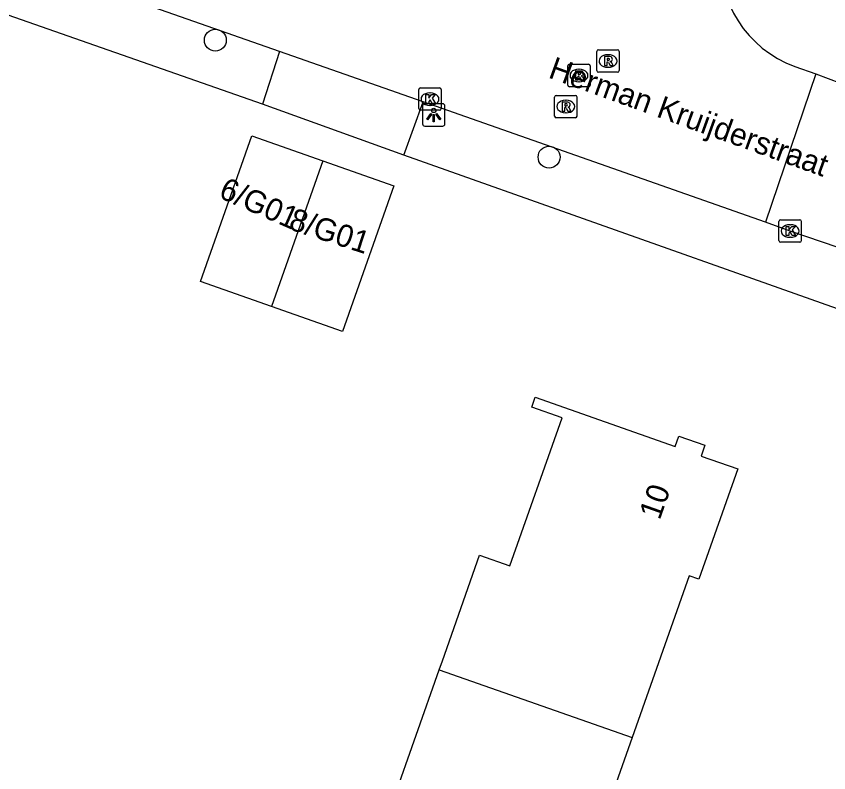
# Model space of a CAD drawing. Extents: x 163268 to 164360, y 381529 to 382285.
# Drawn here: x 163693.84 to 163730.1, y 381686.62 to 381720.39 of the extents above; entities that cross this region are included whole.
import ezdxf

# ---------------------------------------------------------------- set-up
doc = ezdxf.new("R2010")
doc.units = 0
for name, color, linetype in [('IMGEO_Boom', 7, 'Continuous'), ('IMGEO_Kolk', 7, 'Continuous'), ('IMGEO_Lichtpunt', 7, 'Continuous'), ('IMGEO_Openbare_ruimte_label', 7, 'Continuous'), ('IMGEO_Pand', 7, 'Continuous'), ('IMGEO_Pand_nummerreeks', 7, 'Continuous'), ('IMGEO_Rijbaan_lokaal_open', 7, 'Continuous'), ('IMGEO_Rioolput', 7, 'Continuous'), ('IMGEO_Voetpad_open', 7, 'Continuous')]:
    doc.layers.add(name, color=color, linetype=linetype)

msp = doc.modelspace()

# ---------------------------------------------------------------- linework, layer by layer
at = {"layer": 'IMGEO_Boom'}
for centre in [(163702.721, 381719.324), (163717.618, 381714.104)]:
    msp.add_circle(centre, 0.489, dxfattribs=at)
at = {"layer": 'IMGEO_Kolk'}
for p, q in [((163711.802, 381716.267), (163711.802, 381717.119)), ((163711.877, 381717.193), (163712.729, 381717.193)), ((163712.29, 381716.973), (163712.315, 381716.973)), ((163712.803, 381717.119), (163712.803, 381716.267)), ((163712.313, 381716.413), (163712.288, 381716.413)), ((163712.729, 381716.193), (163711.877, 381716.193)), ((163727.876, 381710.379), (163727.876, 381711.231)), ((163727.951, 381711.305), (163728.803, 381711.305)), ((163728.877, 381711.231), (163728.877, 381710.379)), ((163728.364, 381711.085), (163728.389, 381711.085)), ((163728.387, 381710.525), (163728.362, 381710.525)), ((163728.803, 381710.305), (163727.951, 381710.305))]:
    msp.add_line(p, q, dxfattribs=at)
for points in [[(163711.802, 381716.267), (163711.802, 381717.119)], [(163711.877, 381717.193), (163712.729, 381717.193)], [(163712.803, 381717.119), (163712.803, 381716.267)], [(163712.123, 381716.893), (163712.246, 381716.893), (163712.246, 381716.742), (163712.376, 381716.893), (163712.54, 381716.893), (163712.394, 381716.742), (163712.547, 381716.493), (163712.395, 381716.493), (163712.31, 381716.657), (163712.246, 381716.59), (163712.246, 381716.493), (163712.123, 381716.493), (163712.123, 381716.893)], [(163712.729, 381716.193), (163711.877, 381716.193)], [(163727.876, 381710.379), (163727.876, 381711.231)], [(163727.951, 381711.305), (163728.803, 381711.305)], [(163728.877, 381711.231), (163728.877, 381710.379)], [(163728.197, 381711.005), (163728.32, 381711.005), (163728.32, 381710.854), (163728.45, 381711.005), (163728.614, 381711.005), (163728.468, 381710.854), (163728.621, 381710.605), (163728.469, 381710.605), (163728.384, 381710.769), (163728.32, 381710.702), (163728.32, 381710.605), (163728.197, 381710.605), (163728.197, 381711.005)], [(163728.803, 381710.305), (163727.951, 381710.305)]]:
    msp.add_lwpolyline(points, dxfattribs=at)
for centre, start, end in [((163711.879, 381717.117), 91.552, 178.448), ((163711.879, 381717.117), 91.552, 178.448), ((163712.727, 381717.117), 1.552, 88.448), ((163712.727, 381717.117), 1.552, 88.448), ((163711.879, 381716.269), 181.552, 268.448), ((163711.879, 381716.269), 181.552, 268.448), ((163712.727, 381716.269), 271.552, 358.448), ((163712.727, 381716.269), 271.552, 358.448), ((163727.953, 381711.229), 91.552, 178.448), ((163727.953, 381711.229), 91.552, 178.448), ((163728.801, 381711.229), 1.552, 88.448), ((163728.801, 381711.229), 1.552, 88.448), ((163727.953, 381710.381), 181.552, 268.448), ((163727.953, 381710.381), 181.552, 268.448), ((163728.801, 381710.381), 271.552, 358.448), ((163728.801, 381710.381), 271.552, 358.448)]:
    msp.add_arc(centre, 0.0765, start, end, dxfattribs=at)
for centre, major_axis, ratio, start_param, end_param in [((163712.289, 381716.693), (-0.387, 0.002), 0.722429, 4.712389, 7.853982), ((163712.314, 381716.693), (-0.39, 0.002), 0.717154, 1.570796, 4.712389), ((163728.363, 381710.805), (-0.387, 0.002), 0.722429, 4.712389, 7.853982), ((163728.388, 381710.805), (-0.39, 0.002), 0.717154, 1.570796, 4.712389)]:
    msp.add_ellipse(centre, major_axis=major_axis, ratio=ratio, start_param=start_param, end_param=end_param, dxfattribs=at)
at = {"layer": 'IMGEO_Lichtpunt'}
for p, q in [((163711.972, 381716.39), (163711.972, 381715.583)), ((163711.972, 381716.39), (163711.972, 381715.583)), ((163712.874, 381716.485), (163712.066, 381716.485)), ((163712.874, 381716.485), (163712.066, 381716.485)), ((163712.968, 381715.583), (163712.968, 381716.39)), ((163712.968, 381715.583), (163712.968, 381716.39)), ((163712.066, 381715.489), (163712.874, 381715.489)), ((163712.066, 381715.489), (163712.874, 381715.489))]:
    msp.add_line(p, q, dxfattribs=at)
for points in [[(163712.346, 381716.054), (163712.385, 381716.026), (163712.197, 381715.764), (163712.159, 381715.791), (163712.346, 381716.054)], [(163712.448, 381716.006), (163712.495, 381716.006), (163712.495, 381715.684), (163712.448, 381715.684), (163712.448, 381716.006)], [(163712.558, 381716.026), (163712.596, 381716.053), (163712.783, 381715.791), (163712.744, 381715.763), (163712.558, 381716.026)]]:
    msp.add_lwpolyline(points, dxfattribs=at)
msp.add_circle((163712.471, 381716.188), 0.0994, dxfattribs=at)
for centre, start, end in [((163712.066, 381716.39), 90, 180), ((163712.066, 381716.39), 90, 180), ((163712.874, 381716.39), 0, 90), ((163712.874, 381716.39), 0, 90), ((163712.066, 381715.583), 180, 270), ((163712.066, 381715.583), 180, 270), ((163712.874, 381715.583), 270, 0), ((163712.874, 381715.583), 270, 360)]:
    msp.add_arc(centre, 0.0946, start, end, dxfattribs=at)
at = {"layer": 'IMGEO_Pand'}
for points in [[(163705.23, 381707.441), (163702.062, 381708.558), (163704.35, 381715.05), (163707.518, 381713.934)], [(163707.518, 381713.934), (163710.686, 381712.817), (163708.398, 381706.325), (163705.23, 381707.441)], [(163707.518, 381713.934), (163705.23, 381707.441)], [(163712.717, 381691.22), (163712.855, 381691.611), (163714.516, 381696.326), (163715.864, 381695.85), (163718.197, 381702.468), (163716.844, 381702.945), (163716.999, 381703.383), (163723.25, 381701.18), (163723.415, 381701.648), (163724.571, 381701.241), (163724.401, 381700.759), (163726.041, 381700.181), (163724.305, 381695.256), (163723.866, 381695.411), (163721.325, 381688.2)], [(163721.325, 381688.2), (163718.541, 381680.3), (163719.034, 381680.126), (163717.309, 381675.231), (163715.635, 381675.821), (163715.441, 381675.271), (163714.254, 381675.689), (163714.442, 381676.224), (163708.226, 381678.415), (163708.349, 381678.765), (163709.658, 381678.288), (163711.993, 381684.911), (163710.659, 381685.381), (163712.717, 381691.22)], [(163712.717, 381691.22), (163721.325, 381688.2)]]:
    msp.add_lwpolyline(points, dxfattribs=at)
at = {"layer": 'IMGEO_Rijbaan_lokaal_open'}
for points in [[(163705.584, 381718.826), (163697.64, 381721.621)], [(163712, 381716.568), (163705.584, 381718.826)], [(163728.582, 381718.152), (163729.531, 381717.818)], [(163729.531, 381717.818), (163727.274, 381711.194)], [(163729.531, 381717.818), (163730.618, 381717.411), (163736.775, 381715.394), (163761.526, 381706.688), (163770.962, 381703.367), (163772.976, 381702.56), (163774.563, 381702.061)], [(163727.274, 381711.194), (163712, 381716.568)], [(163738.302, 381707.424), (163728.377, 381710.805), (163727.274, 381711.194)]]:
    msp.add_lwpolyline(points, dxfattribs=at)
msp.add_arc((163730.36, 381722.961), 5.127, 175.8918, 249.7129, dxfattribs=at)
at = {"layer": 'IMGEO_Rioolput'}
for p, q in [((163719.748, 381717.968), (163719.748, 381718.82)), ((163719.823, 381718.894), (163720.675, 381718.894)), ((163720.749, 381718.82), (163720.749, 381717.968)), ((163720.236, 381718.674), (163720.261, 381718.674)), ((163718.453, 381717.323), (163718.453, 381718.175)), ((163718.528, 381718.249), (163719.38, 381718.249)), ((163719.454, 381718.175), (163719.454, 381717.323)), ((163720.259, 381718.114), (163720.234, 381718.114)), ((163718.941, 381718.029), (163718.966, 381718.029)), ((163720.675, 381717.894), (163719.823, 381717.894)), ((163718.964, 381717.469), (163718.939, 381717.469)), ((163719.38, 381717.249), (163718.528, 381717.249)), ((163717.863, 381715.935), (163717.863, 381716.787)), ((163717.938, 381716.861), (163718.79, 381716.861)), ((163718.351, 381716.641), (163718.376, 381716.641)), ((163718.864, 381716.787), (163718.864, 381715.935)), ((163718.374, 381716.081), (163718.349, 381716.081)), ((163718.79, 381715.861), (163717.938, 381715.861))]:
    msp.add_line(p, q, dxfattribs=at)
for points in [[(163719.748, 381717.968), (163719.748, 381718.82)], [(163719.823, 381718.894), (163720.675, 381718.894)], [(163720.749, 381718.82), (163720.749, 381717.968)], [(163720.337, 381718.592), (163720.085, 381718.594), (163720.085, 381718.194)], [(163720.263, 381718.513), (163720.209, 381718.513), (163720.209, 381718.432)], [(163720.209, 381718.432), (163720.261, 381718.432)], [(163718.453, 381717.323), (163718.453, 381718.175)], [(163718.528, 381718.249), (163719.38, 381718.249)], [(163719.454, 381718.175), (163719.454, 381717.323)], [(163720.085, 381718.194), (163720.209, 381718.194), (163720.209, 381718.356), (163720.22, 381718.356)], [(163720.267, 381718.327), (163720.338, 381718.194), (163720.478, 381718.194), (163720.413, 381718.32)], [(163719.042, 381717.947), (163718.79, 381717.949), (163718.79, 381717.549)], [(163718.79, 381717.549), (163718.914, 381717.549), (163718.914, 381717.711), (163718.925, 381717.711)], [(163718.968, 381717.868), (163718.914, 381717.868), (163718.914, 381717.787)], [(163718.914, 381717.787), (163718.966, 381717.787)], [(163720.675, 381717.894), (163719.823, 381717.894)], [(163718.972, 381717.682), (163719.043, 381717.549), (163719.183, 381717.549), (163719.118, 381717.675)], [(163719.38, 381717.249), (163718.528, 381717.249)], [(163717.863, 381715.935), (163717.863, 381716.787)], [(163717.938, 381716.861), (163718.79, 381716.861)], [(163718.864, 381716.787), (163718.864, 381715.935)], [(163718.452, 381716.559), (163718.2, 381716.561), (163718.2, 381716.161)], [(163718.2, 381716.161), (163718.324, 381716.161), (163718.324, 381716.323), (163718.335, 381716.323)], [(163718.378, 381716.48), (163718.324, 381716.48), (163718.324, 381716.399)], [(163718.324, 381716.399), (163718.376, 381716.399)], [(163718.382, 381716.294), (163718.453, 381716.161), (163718.593, 381716.161), (163718.528, 381716.287)], [(163718.79, 381715.861), (163717.938, 381715.861)]]:
    msp.add_lwpolyline(points, dxfattribs=at)
for centre, radius, start, end in [((163719.825, 381718.818), 0.0765, 91.552, 178.448), ((163719.825, 381718.818), 0.0765, 91.552, 178.448), ((163720.673, 381718.818), 0.0765, 1.552, 88.448), ((163720.673, 381718.818), 0.0765, 1.552, 88.448), ((163720.245, 381718.621), 0.19, 274.7715, 282.9687), ((163720.269, 381718.417), 0.0964, 77.0061, 93.1865), ((163720.283, 381718.474), 0.0378, 276.6634, 79.6772), ((163720.336, 381718.482), 0.109, 350.3612, 89.416), ((163720.334, 381718.482), 0.112, 277.5842, 350.9817), ((163718.53, 381718.173), 0.0765, 91.552, 178.448), ((163718.53, 381718.173), 0.0765, 91.552, 178.448), ((163719.378, 381718.173), 0.0765, 1.552, 88.448), ((163719.378, 381718.173), 0.0765, 1.552, 88.448), ((163720.219, 381718.303), 0.0533, 26.0293, 88.6989), ((163720.318, 381718.267), 0.108, 29.5134, 73.7905), ((163718.924, 381717.658), 0.0533, 26.0293, 88.6989), ((163718.95, 381717.976), 0.19, 274.7715, 282.9687), ((163718.974, 381717.772), 0.0964, 77.0061, 93.1865), ((163718.988, 381717.829), 0.0378, 276.6634, 79.6772), ((163719.041, 381717.837), 0.109, 350.3612, 89.416), ((163719.039, 381717.837), 0.112, 277.5842, 350.9817), ((163719.023, 381717.622), 0.108, 29.5134, 73.7905), ((163719.825, 381717.97), 0.0765, 181.552, 268.448), ((163719.825, 381717.97), 0.0765, 181.552, 268.448), ((163720.673, 381717.97), 0.0765, 271.552, 358.448), ((163720.673, 381717.97), 0.0765, 271.552, 358.448), ((163718.53, 381717.325), 0.0765, 181.552, 268.448), ((163718.53, 381717.325), 0.0765, 181.552, 268.448), ((163719.378, 381717.325), 0.0765, 271.552, 358.448), ((163719.378, 381717.325), 0.0765, 271.552, 358.448), ((163717.94, 381716.785), 0.0765, 91.552, 178.448), ((163717.94, 381716.785), 0.0765, 91.552, 178.448), ((163718.788, 381716.785), 0.0765, 1.552, 88.448), ((163718.788, 381716.785), 0.0765, 1.552, 88.448), ((163718.334, 381716.27), 0.0533, 26.0293, 88.6989), ((163718.36, 381716.588), 0.19, 274.7715, 282.9687), ((163718.384, 381716.384), 0.0964, 77.0061, 93.1865), ((163718.398, 381716.441), 0.0378, 276.6634, 79.6772), ((163718.451, 381716.449), 0.109, 350.3612, 89.416), ((163718.449, 381716.449), 0.112, 277.5842, 350.9817), ((163718.433, 381716.234), 0.108, 29.5134, 73.7905), ((163717.94, 381715.937), 0.0765, 181.552, 268.448), ((163717.94, 381715.937), 0.0765, 181.552, 268.448), ((163718.788, 381715.937), 0.0765, 271.552, 358.448), ((163718.788, 381715.937), 0.0765, 271.552, 358.448)]:
    msp.add_arc(centre, radius, start, end, dxfattribs=at)
for centre, major_axis, ratio, start_param, end_param in [((163720.235, 381718.394), (-0.387, 0.002), 0.722429, 4.712389, 7.853982), ((163720.26, 381718.394), (-0.39, 0.002), 0.717154, 1.570796, 4.712389), ((163718.94, 381717.749), (-0.387, 0.002), 0.722429, 4.712389, 7.853982), ((163718.965, 381717.749), (-0.39, 0.002), 0.717154, 1.570796, 4.712389), ((163718.35, 381716.361), (-0.387, 0.002), 0.722429, 4.712389, 7.853982), ((163718.375, 381716.361), (-0.39, 0.002), 0.717154, 1.570796, 4.712389)]:
    msp.add_ellipse(centre, major_axis=major_axis, ratio=ratio, start_param=start_param, end_param=end_param, dxfattribs=at)
at = {"layer": 'IMGEO_Voetpad_open'}
for points in [[(163704.828, 381716.464), (163678.538, 381725.673)], [(163705.584, 381718.826), (163704.828, 381716.464)], [(163711.131, 381714.194), (163704.828, 381716.464)], [(163711.131, 381714.194), (163712, 381716.568)], [(163737.338, 381704.902), (163711.131, 381714.194)]]:
    msp.add_lwpolyline(points, dxfattribs=at)

# ---------------------------------------------------------------- texts
at = {"layer": 'IMGEO_Openbare_ruimte_label'}
msp.add_text('Herman Kruijderstraat', height=1, rotation=340.1343, dxfattribs=at).set_placement((163717.54, 381717.667))
at = {"layer": 'IMGEO_Pand_nummerreeks'}
for s, rotation, p in [('6/G01', 336.2752, (163702.823, 381712.32)), ('8/G01', 341.8293, (163705.947, 381710.905)), ('10', 70.5831, (163722.553, 381697.866))]:
    msp.add_text(s, height=1, rotation=rotation, dxfattribs=at).set_placement(p)

doc.saveas('drawing.dxf')
